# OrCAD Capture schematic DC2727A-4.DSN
size Custom
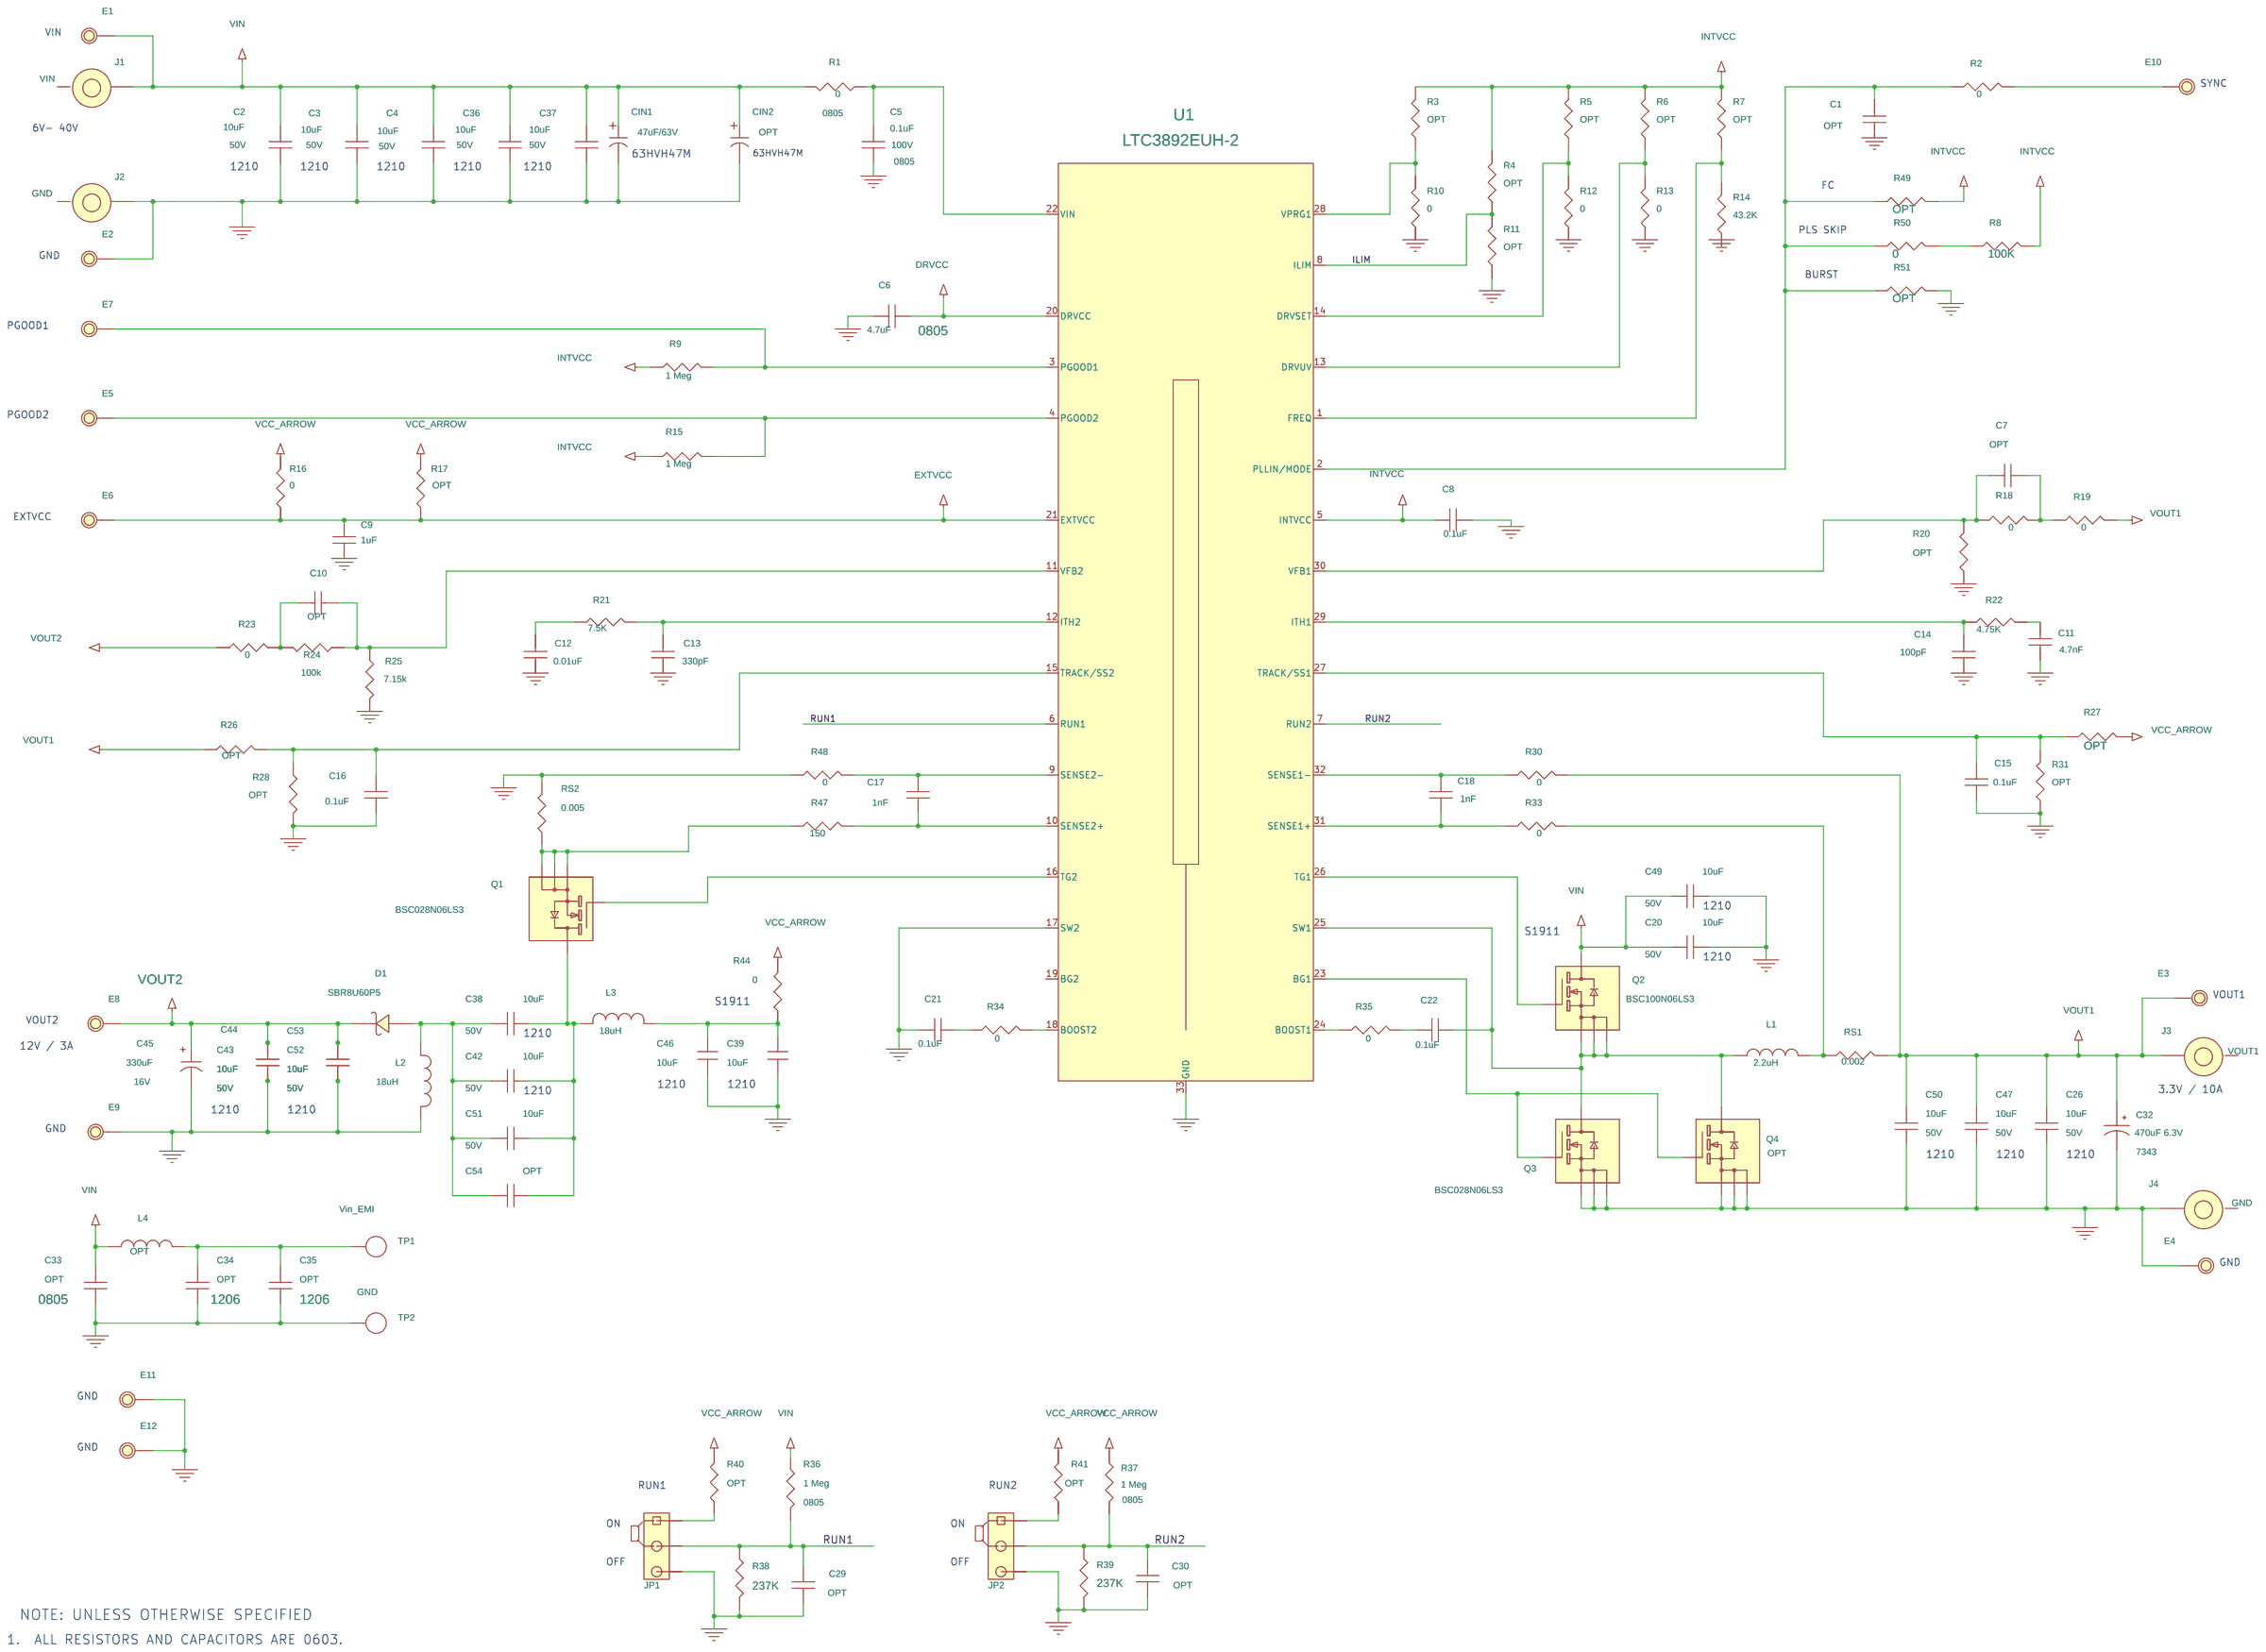
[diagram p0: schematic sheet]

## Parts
C1  OPT  [0603]
C2  10uF  [1210/1812]
C3  10uF  [1210/1812]
C4  10uF  [1210/1812]
C5  0.1uF  [0805]
C6  4.7uF  [0805]
C7  OPT  [0603]
C8  0.1uF  [0603]
C9  1uF  [0603]
C10  OPT  [0603]
C11  4.7nF  [0603]
C12  0.01uF  [0603]
C13  330pF  [0603]
C14  100pF  [0603]
C15  0.1uF  [0603]
C16  0.1uF  [0603]
C17  1nF  [0603]
C18  1nF  [0603]
C20  10uF  [1210/1812]
C21  0.1uF  [0603]
C22  0.1uF  [0603]
C26  10uF  [1210/1812]
C29  OPT  [0603]
C30  OPT  [0603]
C32  470uF 6.3V  [7343]
C33  OPT  [0805]
C34  OPT  [1206]
C35  OPT  [1206]
C36  10uF  [1210/1812]
C37  10uF  [1210/1812]
C38  10uF  [1210/1812]
C39  10uF  [1210/1812]
C42  10uF  [1210/1812]
C43  10uF  [1210/1812]
C44  10uF  [1210/1812]
C45  330uF  [C-10X12.5]
C46  10uF  [1210/1812]
C47  10uF  [1210/1812]
C49  10uF  [1210/1812]
C50  10uF  [1210/1812]
C51  10uF  [1210/1812]
C52  10uF  [1210/1812]
C53  10uF  [1210/1812]
C54  OPT  [1210/1812]
CIN1  47uF/63V  [SANYO-10X10]
CIN2  OPT  [SANYO-10X10]
D1  SBR8U60P5  [POWERDI5-2PIN]
E1  Testpoint  [MILLMAX-2501-2]
E2  Testpoint  [MILLMAX-2501-2]
E3  Testpoint  [MILLMAX-2501-2]
E4  Testpoint  [MILLMAX-2501-2]
E5  Testpoint  [MILLMAX-2501-2]
E6  Testpoint  [MILLMAX-2501-2]
E7  Testpoint  [MILLMAX-2501-2]
E8  Testpoint  [MILLMAX-2501-2]
E9  Testpoint  [MILLMAX-2501-2]
E10  Testpoint  [MILLMAX-2501-2]
E11  Testpoint  [MILLMAX-2501-2]
E12  Testpoint  [MILLMAX-2501-2]
J1  VIN  [KEY-575-4]
J2  GND  [KEY-575-4]
J3  VOUT1  [KEY-575-4]
J4  GND  [KEY-575-4]
JP1  HDR1X3  [commcon2802s03g2]
JP2  HDR1X3  [commcon2802s03g2]
L1  2.2uH  [IND-7443936]
L2  18uH  [IND-PG0936]
L3  18uH  [IND-PG0936]
L4  OPT  [XAL7070]
Q1  BSC028N06LS3  [WPACKV]
Q2  BSC100N06LS3  [WPACKV]
Q3  BSC028N06LS3  [WPACKV]
Q4  OPT  [WPACKV]
R1  0  [0805]
R2  0  [0603]
R3  OPT  [0603]
R4  OPT  [0603]
R5  OPT  [0603]
R6  OPT  [0603]
R7  OPT  [0603]
R8  100K  [0603]
R9  1 Meg  [0603]
R10  0  [0603]
R11  OPT  [0603]
R12  0  [0603]
R13  0  [0603]
R14  43.2K  [0603]
R15  1 Meg  [0603]
R16  0  [0603]
R17  OPT  [0603]
R18  0  [0603]
R19  0  [0603]
R20  OPT  [0603]
R21  7.5K  [0603]
R22  4.75K  [0603]
R23  0  [0603]
R24  100k  [0603]
R25  7.15k  [0603]
R26  OPT  [0603]
R27  OPT  [0603]
R28  OPT  [0603]
R30  0  [0603]
R31  OPT  [0603]
R33  0  [0603]
R34  0  [0603]
R35  0  [0603]
R36  1 Meg  [0805]
R37  1 Meg  [0805]
R38  237K  [0603]
R39  237K  [0603]
R40  OPT  [0603]
R41  OPT  [0603]
R44  0  [R-S1911]
R47  150  [0603]
R48  0  [0603]
R49  OPT  [0603]
R50  0  [0603]
R51  OPT  [0603]
RS1  0.002  [RES-KRL3216]
RS2  0.005  [RES-KRL3216]
TP1  Testpoint  [PAD-5X5MM]
TP2  Testpoint  [PAD-5X5MM]
U1  LTC3892EUH-2  [QFN32UH-5X5]
XJP1  2mm Ctrs.
XJP2  2mm Ctrs.

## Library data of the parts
C1 C6-C18 C21 C22 C29 C30 C34 C35 = CAP_NP_0: VOLTAGE: ( Opt. )
C2-C4 C20 C26 C33 C36-C38 C42-C44 C47 C49-C54 = CAP_NP_0: VOLTAGE: 50V
C5 = CAP_NP_0: VOLTAGE: 100V
C32 = CAP_POL
C39 C46 = CAP1812: 1ST PART FIELD: 50V
C45 = CAP-CE-6.3X5_0.4: 1ST PART FIELD: 16V; 5TH PART FIELD: 63CE10FS
CIN1 CIN2 = CAP
D1 = PDS1040: 5TH PART FIELD: PDS1045-13
E1-E12 = MillMax-2501_1
J1 J3 = E_7
J2 J4 = E_6
JP1 JP2 = Commcon2802s03g2: 11th Part Field: OFF; 12th Part Field: RUN; 9th Part Field: ON
L1 L4 = INDUCTOR: manufacturing: Coilcraft SER1360-472KL
L2 L3 = IND-IHLP-4040DZ-11
Q1-Q4 = 2N7002_26
R1-R28 R30 R31 R33-R41 R44 R47-R51 RS1 RS2 = R_1: %: 0.1%
TP1 = mill-max-2308-2_0: 5th Part Field: 2501-2; 9th Part Field: Vin_EMI
TP2 = mill-max-2308-2_0: 5th Part Field: 2501-2; 9th Part Field: GND
U1 = LTC3892EUH-2_0
XJP1 XJP2 = CommconCCIJ2MM-138G

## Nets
GND: C1.1 C2.1 C3.1 C4.1 C5.1 C6.1 C8.2 C9.1 C11.1 C12.1 C13.1 C14.1 C15.1 C16.1 C20.1 C21.2 C26.1 C29.1 C30.1 C32.2 C33.1 C34.1 C35.1 C36.1 C37.1 C39.2 C43.1 C44.1 C45.2 C46.2 C47.1 C49.1 C50.1 C52.1 C53.1 CIN1.2 CIN2.2 E2.1 E4.1 E9.1 E11.1 E12.1 J2.1(A) J4.1(A) JP1.3 JP2.3 L2.2 Q3.1 Q3.2 Q3.3 Q4.1 Q4.2 Q4.3 R10.2 R11.2 R12.2 R13.2 R14.2 R20.2 R25.2 R28.2 R31.2 R38.2 R39.2 R48.1 R51.2 RS2.2 TP2.1 U1.17(SW2) U1.33(GND)
VIN: C2.2 C3.2 C4.2 C20.2 C33.2 C36.2 C37.2 C49.2 CIN1.1 CIN2.1 E1.1 J1.1(A) L4.2 Q2.5 R1.2 R36.1 R37.1 R40.2 R41.2 R44.2
DRVCC: C6.2 U1.20(DRVCC)
EXTVCC: C9.2 E6.1 R16.1 R17.1 U1.21(EXTVCC)
ILIM: R4.2 R11.1 U1.8(ILIM)
INTVCC: C8.1 R3.1 R4.1 R5.1 R6.1 R7.1 R8.2 R9.1 R15.1 R49.2 U1.5(INTVCC)
RUN1: C29.2 JP1.2 R36.2 R38.1 U1.6(RUN1)
RUN2: C30.2 JP2.2 R37.2 R39.1 U1.7(RUN2)
VOUT1: C26.2 C32.1 C47.2 C50.2 E3.1 J3.1(A) R17.2 R19.2 R26.1 R30.2 RS1.2
VOUT2: C43.2 C44.2 C45.1 C52.2 C53.2 D1.1 E8.1 R16.2 R23.1 R27.1
N16828492: C15.2 R27.2 R31.1 U1.27(TRACK/SS1)
N16828498: R7.2 R14.1 U1.1(FREQ)
N16828517: C13.2 R21.1 U1.12(ITH2)
N16828519: C16.2 R26.2 R28.1 U1.15(TRACK/SS2)
N16828521: C10.2 R24.1 R25.1 U1.11(VFB2)
N16828531: C22.1 L1.1 Q2.1 Q2.2 Q2.3 Q3.5 Q4.5 U1.25(SW1)
N16828567: L1.2 R33.2 RS1.1
N16828575: C7.1 R18.1 R20.1 U1.30(VFB1)
N16828658: R3.2 R10.1 U1.28(VPRG1)
N16828662: C7.2 R18.2 R19.1
N16828766: Q3.4 Q4.4 U1.23(BG1)
N16828778: Q2.4 U1.26(TG1)
N16828782: C5.2 R1.1 U1.22(VIN)
N16828851: C12.2 R21.2
N16828855: C1.2 R2.1 R49.1 R50.1 R51.1 U1.2(PLLIN/MODE)
N16828857: C17.2 R48.2 U1.9(SENSE2-)
N16828915: C17.1 R47.2 U1.10(SENSE2+)
N16829005: R34.2 U1.18(BOOST2)
N16829018: E7.1 R9.2 U1.3(PGOOD1)
N16829089: R6.2 R13.1 U1.13(DRVUV)
N16829123: R35.1 U1.24(BOOST1)
N16829133: E5.1 R15.2 U1.4(PGOOD2)
N16829141: R5.2 R12.1 U1.14(DRVSET)
N16829379: R8.1 R50.2
N16829443: E10.1 R2.2
N16829525: C11.2 R22.2
N16829584: C10.1 R23.2 R24.2
N16829662: C18.2 R30.1 U1.32(SENSE1-)
N16829670: C14.2 R22.1 U1.29(ITH1)
N16829674: C18.1 R33.1 U1.31(SENSE1+)
N17103102: C21.1 R34.1
N17108280: C22.2 R35.2
N17118608: JP1.1 R40.1
N17119054: JP2.1 R41.1
N17143504: C34.2 C35.2 L4.1 TP1.1
N17233107: Q1.1 Q1.2 Q1.3 R47.1 RS2.1
N17233222: C39.1 C46.1 L3.1 R44.1
N17233260: C38.2 C42.2 C51.2 C54.2 D1.2 L2.1
N17258314: C38.1 C42.1 C51.1 C54.1 L3.2 Q1.5
N17258331: Q1.4 U1.16(TG2)

Not connected (* = marked no-connect by the designer): U1 19(BG2)

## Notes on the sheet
- VIN
- SYNC
- 6V- 40V
- 63HVH47M
- 63HVH47M
- 1210
- 1210
- 1210
- 1210
- 1210
- FC
- PLS SKIP
- GND
- BURST
- PGOOD1
- PGOOD2
- EXTVCC
- 1210
- S1911
- 1210
- S1911
- VOUT1
- VOUT2
- 12V / 3A
- 1210
- 1210
- 1210
- 1210
- 3.3V / 10A
- 1210
- 1210
- GND
- 1210
- 1210
- 1210
- GND
- GND
- GND
- RUN1
- RUN2
- ON
- ON
- OFF
- OFF
- NOTE: UNLESS OTHERWISE SPECIFIED
- 1.  ALL RESISTORS AND CAPACITORS ARE 0603.
